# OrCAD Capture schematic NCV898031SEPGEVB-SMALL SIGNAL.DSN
size A; title: NCV898031 SEPIC EVALUATION BOARD (NCV898031SEPGEVB)
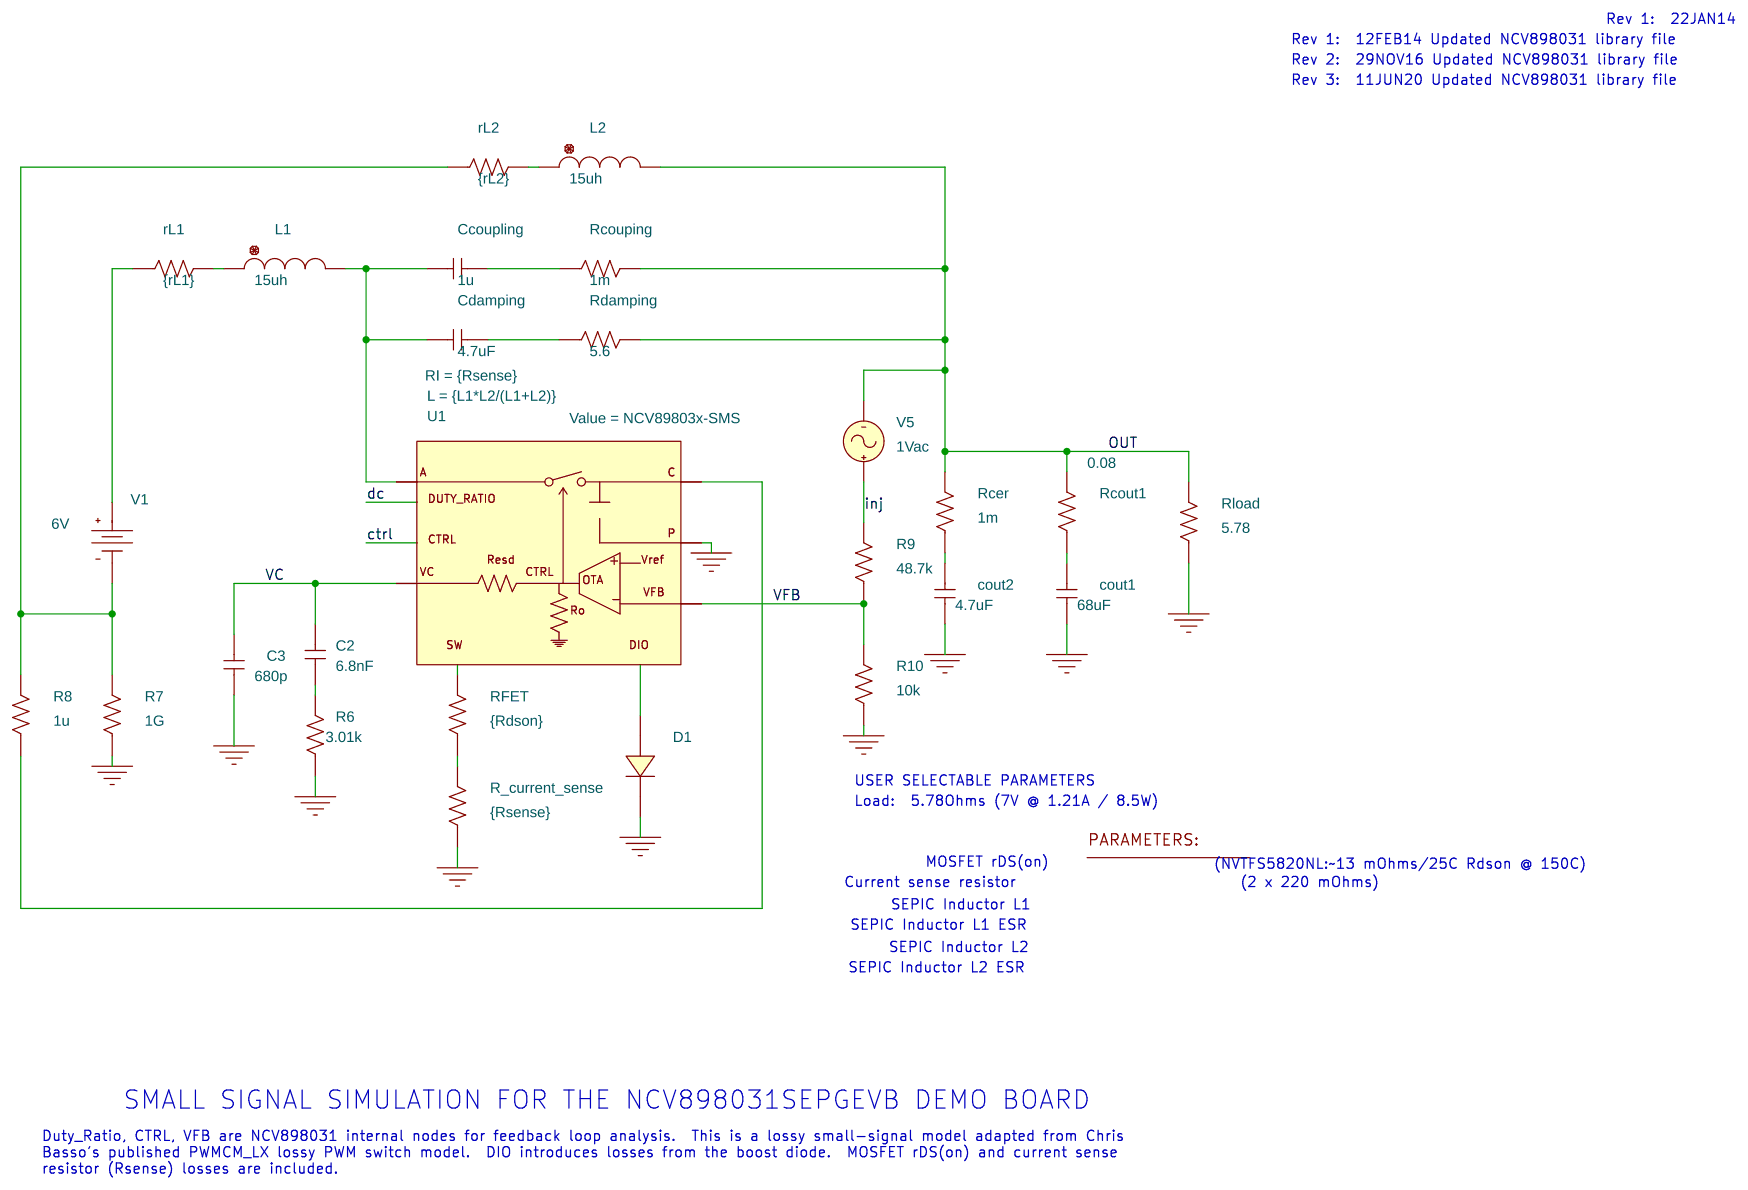
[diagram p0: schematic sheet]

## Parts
1  PARAM
C2  6.8nF  [RAD/CK05]
C3  680p  [RAD/CK05]
Ccoupling  1u  [RAD/CK05]
Cdamping  4.7uF  [RAD/CK05]
cout1  68uF  [RAD/CK05]
cout2  4.7uF  [RAD/CK05]
D1  DMBRS360T3  [DO41]
L1  15uh  [DISC/.350x.175/LS.200x.100/.034]
L2  15uh  [DISC/.350x.175/LS.200x.100/.034]
R6  3.01k  [AX/RC05]
R7  1G  [AX/RC05]
R8  1u  [AX/RC05]
R9  48.7k  [AX/RC05]
R10  10k  [AX/RC05]
R_current_sense  {Rsense}  [AX/RC05]
Rcer  1m  [AX/RC05]
Rcouping  1m  [AX/RC05]
Rcout1  0.08  [AX/RC05]
Rdamping  5.6  [AX/RC05]
RFET  {Rdson}  [AX/RC05]
rL1  {rL1}  [AX/RC05]
rL2  {rL2}  [AX/RC05]
Rload  5.78  [AX/RC05]
U1  NCV89803x-SMS
V1  VDC
V5  VAC

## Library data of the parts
1 = PARAM: L1: 15uH; L2: 15uH; Rdson: 25m; Rsense: 0.110; rL1: 120m; rL2: 120m
C2 C3 Ccoupling Cdamping cout1 cout2 = C
D1 = DMBRS360T3
L1 L2 = L
R6-R10 R_current_sense Rcer Rcouping Rcout1 Rdamping RFET rL1 rL2 Rload = R
U1 = NCV89803x-SMS: L: {L1*L2/(L1+L2)}; RI: {Rsense}
V1 = VDC: DC: 6V
V5 = VAC: ACMAG: 1Vac

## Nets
0: C3.1 cout1.1 cout2.1 D1.1(C) R6.1 R7.1 R10.1 R_current_sense.1 Rload.1 U1.3(P)
ctrl: U1.5(CTRL)
dc: U1.9(DUTY_RATIO)
inj: R9.2 V5.1(+)
OUT: L2.2 Rcer.2 Rcouping.2 Rcout1.2 Rdamping.2 Rload.2 V5.2(-)
VC: C2.2 C3.2 U1.6(VC)
VFB: R9.1 R10.2 U1.4(VFB)
N1197263: Cdamping.2 Rdamping.1
N1197269: Ccoupling.2 Rcouping.1
N1197301: Ccoupling.1 Cdamping.1 L1.2 U1.1(A)
N1197305: rL1.1 V1.0(+)
N1197315: R7.2 R8.2 rL2.1 V1.1(-)
N1197337: R8.1 U1.2(C)
N1197547: RFET.2 U1.7(SW)
N1197553: D1.2(A) U1.8(DIO)
N1197733: cout2.2 Rcer.1
N1197759: cout1.2 Rcout1.1
N1198115: C2.1 R6.2
N1198175: R_current_sense.2 RFET.1
N1198211: L1.1 rL1.2
N1198217: L2.1 rL2.2

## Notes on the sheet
- Rev 1:  22JAN14
- Rev 1:  12FEB14 Updated NCV898031 library file
- Rev 2:  29NOV16 Updated NCV898031 library file
- Rev 3:  11JUN20 Updated NCV898031 library file
- USER SELECTABLE PARAMETERS
- Load:  5.78Ohms (7V @ 1.21A / 8.5W)
- MOSFET rDS(on)
- (NVTFS5820NL:~13 mOhms/25C Rdson @ 150C)
- Current sense resistor
- (2 x 220 mOhms)
- SEPIC Inductor L1
- SEPIC Inductor L1 ESR
- SEPIC Inductor L2
- SEPIC Inductor L2 ESR
- SMALL SIGNAL SIMULATION FOR THE NCV898031SEPGEVB DEMO BOARD
- Duty_Ratio, CTRL, VFB are NCV898031 internal nodes for feedback loop analysis.  This is a lossy small-signal model adapted from Chris
  Basso's published PWMCM_LX lossy PWM switch model.  DIO introduces losses from the boost diode.  MOSFET rDS(on) and current sense
  resistor (Rsense) losses are included.
